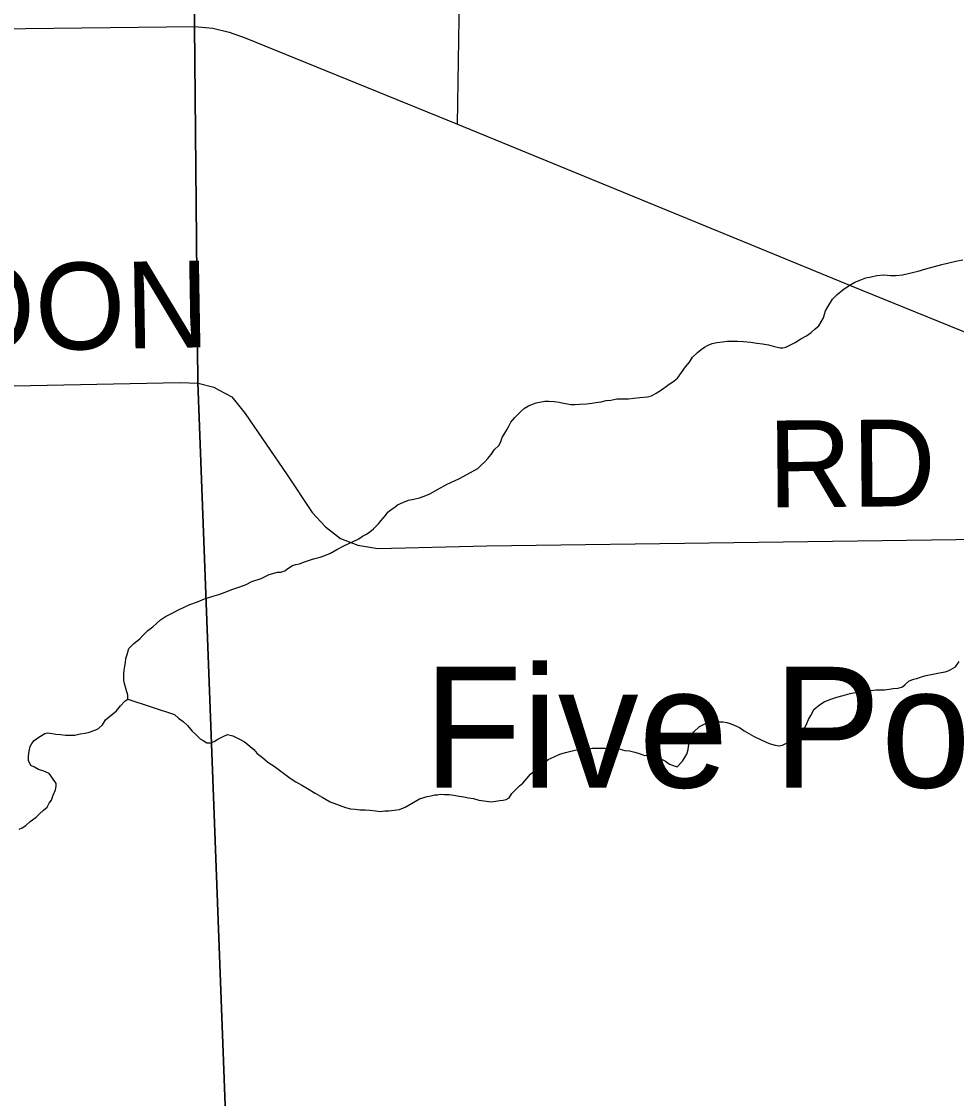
# Model space of a CAD drawing. Extents: x -59 to 82, y -3 to 49.
# Drawn here: x -50.668 to -50.056, y 43.234 to 43.939 of the extents above; entities that cross this region are included whole.
import ezdxf

# ---------------------------------------------------------------- set-up
doc = ezdxf.new("R2010")
doc.units = 0
for name, color, linetype in [('GM_X_Corporation', 7, 'Continuous'), ('GM_X_County_Road', 7, 'Continuous'), ('GM_X_County_Road_Text', 7, 'Continuous'), ('GM_X_Minor_River', 7, 'Continuous'), ('GM_X_State_Route', 7, 'Continuous'), ('GM_X_Township_Road', 7, 'Continuous'), ('GM_X_Unincorporated_Text', 7, 'Continuous')]:
    doc.layers.add(name, color=color, linetype=linetype)

msp = doc.modelspace()

# ---------------------------------------------------------------- linework, layer by layer
at = {"layer": 'GM_X_Corporation'}
for p, q in [((-50.55461, 43.9364), (-50.55326, 44.22179)), ((-50.55326, 44.22179), (-50.55461, 43.9364)), ((-50.55225, 43.7029), (-50.55461, 43.9364)), ((-50.55461, 43.9364), (-50.55225, 43.7029)), ((-50.52912, 43.09163), (-50.55225, 43.7029)), ((-50.55225, 43.7029), (-50.52912, 43.09163))]:
    msp.add_line(p, q, dxfattribs=at)
at = {"layer": 'GM_X_County_Road'}
for p, q in [((-50.75944, 43.69919), (-50.56412, 43.70278)), ((-50.56412, 43.70278), (-50.55205, 43.70234)), ((-50.55205, 43.70234), (-50.54176, 43.69974)), ((-50.54176, 43.69974), (-50.53843, 43.69794)), ((-50.53843, 43.69794), (-50.53011, 43.69342)), ((-50.53011, 43.69342), (-50.52143, 43.68269)), ((-50.52143, 43.68269), (-50.49381, 43.6425)), ((-50.49381, 43.6425), (-50.4776, 43.61784)), ((-50.4776, 43.61784), (-50.46893, 43.60848)), ((-50.46893, 43.60848), (-50.45912, 43.60071)), ((-50.45912, 43.60071), (-50.4477, 43.59637)), ((-50.36324, 43.59592), (-50.00652, 43.60075)), ((-50.4477, 43.59637), (-50.43469, 43.59432)), ((-50.43469, 43.59432), (-50.36324, 43.59592))]:
    msp.add_line(p, q, dxfattribs=at)
at = {"layer": 'GM_X_Minor_River'}
for p, q in [((-50.07058, 43.77883), (-50.06565, 43.78001)), ((-50.06565, 43.78001), (-50.06111, 43.78118)), ((-50.06111, 43.78118), (-50.05656, 43.78235)), ((-50.05656, 43.78235), (-50.05201, 43.78314)), ((-50.11191, 43.77208), (-50.10812, 43.77287)), ((-50.10812, 43.77287), (-50.10357, 43.77328)), ((-50.10357, 43.77328), (-50.09939, 43.77293)), ((-50.09939, 43.77293), (-50.09559, 43.77295)), ((-50.09559, 43.77295), (-50.09142, 43.77336)), ((-50.09142, 43.77336), (-50.08118, 43.77572)), ((-50.08118, 43.77572), (-50.07626, 43.77727)), ((-50.07626, 43.77727), (-50.07058, 43.77883)), ((-50.13045, 43.76358), (-50.1263, 43.76627)), ((-50.1263, 43.76627), (-50.12252, 43.76858)), ((-50.12252, 43.76858), (-50.11873, 43.77013)), ((-50.11873, 43.77013), (-50.11532, 43.77129)), ((-50.11532, 43.77129), (-50.11191, 43.77208)), ((-50.13724, 43.75745), (-50.13422, 43.76051)), ((-50.13422, 43.76051), (-50.13045, 43.76358)), ((-50.14173, 43.74981), (-50.14023, 43.75249)), ((-50.14023, 43.75249), (-50.13724, 43.75745)), ((-50.14471, 43.74257), (-50.14321, 43.74524)), ((-50.14321, 43.74524), (-50.14247, 43.74753)), ((-50.14247, 43.74753), (-50.14173, 43.74981)), ((-50.15111, 43.73568), (-50.14847, 43.73798)), ((-50.14847, 43.73798), (-50.14621, 43.7399)), ((-50.14621, 43.7399), (-50.14471, 43.74257)), ((-50.16169, 43.72914), (-50.15791, 43.73145)), ((-50.15791, 43.73145), (-50.15413, 43.73338)), ((-50.15413, 43.73338), (-50.15111, 43.73568)), ((-50.22543, 43.72261), (-50.22317, 43.72453)), ((-50.22317, 43.72453), (-50.2209, 43.72606)), ((-50.2209, 43.72606), (-50.21863, 43.72722)), ((-50.21863, 43.72722), (-50.21598, 43.72838)), ((-50.21598, 43.72838), (-50.21295, 43.72916)), ((-50.21295, 43.72916), (-50.20916, 43.72957)), ((-50.20916, 43.72957), (-50.20613, 43.72997)), ((-50.20613, 43.72997), (-50.20271, 43.72999)), ((-50.20271, 43.72999), (-50.19929, 43.73002)), ((-50.19929, 43.73002), (-50.19549, 43.72967)), ((-50.19549, 43.72967), (-50.19055, 43.72932)), ((-50.19055, 43.72932), (-50.18675, 43.72859)), ((-50.18675, 43.72859), (-50.18295, 43.72823)), ((-50.18295, 43.72823), (-50.17915, 43.7275)), ((-50.17915, 43.7275), (-50.1761, 43.72676)), ((-50.1761, 43.72676), (-50.17344, 43.72602)), ((-50.17344, 43.72602), (-50.17154, 43.72565)), ((-50.17154, 43.72565), (-50.16964, 43.72566)), ((-50.16964, 43.72566), (-50.16774, 43.72606)), ((-50.16774, 43.72606), (-50.16509, 43.72722)), ((-50.16509, 43.72722), (-50.16169, 43.72914)), ((-50.23069, 43.71611), (-50.22883, 43.71955)), ((-50.22883, 43.71955), (-50.22543, 43.72261)), ((-50.23859, 43.70579), (-50.23333, 43.71305)), ((-50.23333, 43.71305), (-50.23069, 43.71611)), ((-50.24501, 43.70118), (-50.24085, 43.70387)), ((-50.24085, 43.70387), (-50.23859, 43.70579)), ((-50.25558, 43.69426), (-50.25255, 43.6958)), ((-50.25255, 43.6958), (-50.24916, 43.69811)), ((-50.24916, 43.69811), (-50.24501, 43.70118)), ((-50.33603, 43.68761), (-50.33338, 43.68877)), ((-50.33338, 43.68877), (-50.33111, 43.68955)), ((-50.33111, 43.68955), (-50.32883, 43.68995)), ((-50.32883, 43.68995), (-50.32542, 43.69073)), ((-50.32542, 43.69073), (-50.32276, 43.69075)), ((-50.32276, 43.69075), (-50.31934, 43.69039)), ((-50.31934, 43.69039), (-50.31592, 43.69004)), ((-50.31592, 43.69004), (-50.31326, 43.68929)), ((-50.31326, 43.68929), (-50.3106, 43.68893)), ((-50.3106, 43.68893), (-50.30832, 43.68857)), ((-50.30832, 43.68857), (-50.30566, 43.68859)), ((-50.30566, 43.68859), (-50.30262, 43.68861)), ((-50.30262, 43.68861), (-50.29807, 43.68902)), ((-50.29807, 43.68902), (-50.29465, 43.68942)), ((-50.29465, 43.68942), (-50.292, 43.68982)), ((-50.292, 43.68982), (-50.28858, 43.69023)), ((-50.28858, 43.69023), (-50.28517, 43.69101)), ((-50.28517, 43.69101), (-50.28214, 43.69141)), ((-50.28214, 43.69141), (-50.27835, 43.6922)), ((-50.27835, 43.6922), (-50.27455, 43.69223)), ((-50.27455, 43.69223), (-50.27075, 43.69225)), ((-50.27075, 43.69225), (-50.26734, 43.69266)), ((-50.26734, 43.69266), (-50.26317, 43.69307)), ((-50.26317, 43.69307), (-50.25823, 43.69348)), ((-50.25823, 43.69348), (-50.25558, 43.69426)), ((-50.34508, 43.67995), (-50.34282, 43.68224)), ((-50.34282, 43.68224), (-50.34094, 43.68416)), ((-50.34094, 43.68416), (-50.33867, 43.68607)), ((-50.33867, 43.68607), (-50.33603, 43.68761)), ((-50.34921, 43.67383), (-50.34771, 43.67688)), ((-50.34771, 43.67688), (-50.34508, 43.67995)), ((-50.35333, 43.66696), (-50.35145, 43.66963)), ((-50.35145, 43.66963), (-50.35033, 43.67192)), ((-50.35033, 43.67192), (-50.34921, 43.67383)), ((-50.3582, 43.65894), (-50.35556, 43.66162)), ((-50.35556, 43.66162), (-50.35444, 43.66353)), ((-50.35444, 43.66353), (-50.35333, 43.66696)), ((-50.36459, 43.65091), (-50.36271, 43.6532)), ((-50.36271, 43.6532), (-50.36046, 43.65588)), ((-50.36046, 43.65588), (-50.3582, 43.65894)), ((-50.38159, 43.63976), (-50.36911, 43.64669)), ((-50.36911, 43.64669), (-50.36723, 43.64861)), ((-50.36723, 43.64861), (-50.36459, 43.65091)), ((-50.38915, 43.63628), (-50.38159, 43.63976)), ((-50.4005, 43.63012), (-50.39558, 43.63282)), ((-50.39558, 43.63282), (-50.38915, 43.63628)), ((-50.4183, 43.62429), (-50.41451, 43.62584)), ((-50.41451, 43.62584), (-50.4111, 43.62663)), ((-50.4111, 43.62663), (-50.40731, 43.62741)), ((-50.40731, 43.62741), (-50.40428, 43.62857)), ((-50.40428, 43.62857), (-50.4005, 43.63012)), ((-50.42962, 43.61585), (-50.42812, 43.61814)), ((-50.42812, 43.61814), (-50.42586, 43.61968)), ((-50.42586, 43.61968), (-50.42359, 43.62121)), ((-50.42359, 43.62121), (-50.4217, 43.62275)), ((-50.4217, 43.62275), (-50.4183, 43.62429)), ((-50.43414, 43.61049), (-50.43263, 43.61241)), ((-50.43263, 43.61241), (-50.42962, 43.61585)), ((-50.44205, 43.60359), (-50.43979, 43.60513)), ((-50.43979, 43.60513), (-50.43752, 43.60705)), ((-50.43752, 43.60705), (-50.43414, 43.61049)), ((-50.45642, 43.59627), (-50.45113, 43.59859)), ((-50.45113, 43.59859), (-50.44696, 43.60052)), ((-50.44696, 43.60052), (-50.4447, 43.60243)), ((-50.4447, 43.60243), (-50.44205, 43.60359)), ((-50.47231, 43.58855), (-50.46928, 43.58971)), ((-50.46928, 43.58971), (-50.4655, 43.59126)), ((-50.4655, 43.59126), (-50.46134, 43.59357)), ((-50.46134, 43.59357), (-50.45642, 43.59627)), ((-50.49351, 43.58118), (-50.49049, 43.5831)), ((-50.49049, 43.5831), (-50.48822, 43.58388)), ((-50.48822, 43.58388), (-50.48594, 43.58427)), ((-50.48594, 43.58427), (-50.48329, 43.58543)), ((-50.48329, 43.58543), (-50.48064, 43.58621)), ((-50.48064, 43.58621), (-50.47799, 43.58699)), ((-50.47799, 43.58699), (-50.47572, 43.58777)), ((-50.47572, 43.58777), (-50.47231, 43.58855)), ((-50.51093, 43.57459), (-50.50563, 43.57729)), ((-50.50563, 43.57729), (-50.50033, 43.57885)), ((-50.50033, 43.57885), (-50.49805, 43.57886)), ((-50.49805, 43.57886), (-50.4954, 43.57964)), ((-50.4954, 43.57964), (-50.49351, 43.58118)), ((-50.52948, 43.56761), (-50.52493, 43.56917)), ((-50.52493, 43.56917), (-50.52077, 43.57072)), ((-50.52077, 43.57072), (-50.51699, 43.57264)), ((-50.51699, 43.57264), (-50.51093, 43.57459)), ((-50.55258, 43.55947), (-50.54804, 43.5614)), ((-50.54804, 43.5614), (-50.54311, 43.56295)), ((-50.54311, 43.56295), (-50.53856, 43.56413)), ((-50.53856, 43.56413), (-50.5344, 43.56568)), ((-50.5344, 43.56568), (-50.52948, 43.56761)), ((-50.56506, 43.55406), (-50.56128, 43.55598)), ((-50.56128, 43.55598), (-50.5575, 43.55753)), ((-50.5575, 43.55753), (-50.55258, 43.55947)), ((-50.57942, 43.54521), (-50.57678, 43.54751)), ((-50.57678, 43.54751), (-50.57338, 43.54981)), ((-50.57338, 43.54981), (-50.5696, 43.55174)), ((-50.5696, 43.55174), (-50.56506, 43.55406)), ((-50.58809, 43.53754), (-50.58508, 43.54061)), ((-50.58508, 43.54061), (-50.58168, 43.54291)), ((-50.58168, 43.54291), (-50.57942, 43.54521)), ((-50.59412, 43.53218), (-50.59224, 43.53371)), ((-50.59224, 43.53371), (-50.59035, 43.53524)), ((-50.59035, 43.53524), (-50.58809, 43.53754)), ((-50.59862, 43.52492), (-50.59751, 43.52873)), ((-50.59751, 43.52873), (-50.59412, 43.53218)), ((-50.60008, 43.5173), (-50.59972, 43.51959)), ((-50.59972, 43.51959), (-50.59936, 43.52225)), ((-50.59936, 43.52225), (-50.59862, 43.52492)), ((-50.0567, 43.51693), (-50.05445, 43.52037)), ((-50.6008, 43.51235), (-50.60044, 43.51464)), ((-50.60078, 43.50969), (-50.6008, 43.51235)), ((-50.60044, 43.51464), (-50.60008, 43.5173)), ((-50.07602, 43.51109), (-50.06616, 43.51306)), ((-50.06616, 43.51306), (-50.06351, 43.51346)), ((-50.06351, 43.51346), (-50.06161, 43.51423)), ((-50.06161, 43.51423), (-50.05972, 43.51501)), ((-50.05972, 43.51501), (-50.0567, 43.51693)), ((-50.60076, 43.50779), (-50.60078, 43.50969)), ((-50.60037, 43.50589), (-50.60076, 43.50779)), ((-50.5992, 43.5021), (-50.60037, 43.50589)), ((-50.09153, 43.50375), (-50.08964, 43.50529)), ((-50.08964, 43.50529), (-50.087, 43.50759)), ((-50.087, 43.50759), (-50.08397, 43.50875)), ((-50.08397, 43.50875), (-50.08208, 43.50914)), ((-50.08208, 43.50914), (-50.07905, 43.51031)), ((-50.07905, 43.51031), (-50.07602, 43.51109)), ((-50.59803, 43.4983), (-50.5992, 43.5021)), ((-50.59801, 43.49564), (-50.59803, 43.4983)), ((-50.13438, 43.49699), (-50.13021, 43.49816)), ((-50.13021, 43.49816), (-50.12567, 43.49933)), ((-50.12567, 43.49933), (-50.12339, 43.49973)), ((-50.12339, 43.49973), (-50.12112, 43.50013)), ((-50.12112, 43.50013), (-50.11884, 43.50052)), ((-50.11884, 43.50052), (-50.11657, 43.50092)), ((-50.11657, 43.50092), (-50.11429, 43.50131)), ((-50.11429, 43.50131), (-50.11201, 43.50133)), ((-50.11201, 43.50133), (-50.10898, 43.50173)), ((-50.10898, 43.50173), (-50.10594, 43.50175)), ((-50.10594, 43.50175), (-50.10328, 43.50177)), ((-50.10328, 43.50177), (-50.10025, 43.50217)), ((-50.10025, 43.50217), (-50.09759, 43.50257)), ((-50.09759, 43.50257), (-50.09418, 43.50298)), ((-50.09418, 43.50298), (-50.09153, 43.50375)), ((-50.60554, 43.48799), (-50.60291, 43.49142)), ((-50.60291, 43.49142), (-50.5999, 43.49449)), ((-50.5999, 43.49449), (-50.59801, 43.49564)), ((-50.59801, 43.49564), (-50.56755, 43.48559)), ((-50.14951, 43.4889), (-50.14573, 43.49197)), ((-50.14573, 43.49197), (-50.14271, 43.49389)), ((-50.14271, 43.49389), (-50.13893, 43.49544)), ((-50.13893, 43.49544), (-50.13438, 43.49699)), ((-50.61271, 43.48223), (-50.60554, 43.48799)), ((-50.56755, 43.48559), (-50.56487, 43.48333)), ((-50.15287, 43.48241), (-50.15137, 43.48508)), ((-50.15137, 43.48508), (-50.15025, 43.48699)), ((-50.15025, 43.48699), (-50.14951, 43.4889)), ((-50.61722, 43.47649), (-50.61458, 43.47879)), ((-50.61458, 43.47879), (-50.61271, 43.48223)), ((-50.56487, 43.48333), (-50.56182, 43.48107)), ((-50.56182, 43.48107), (-50.55914, 43.47842)), ((-50.55914, 43.47842), (-50.55607, 43.47464)), ((-50.22799, 43.47428), (-50.22422, 43.47773)), ((-50.22422, 43.47773), (-50.22082, 43.47965)), ((-50.22082, 43.47965), (-50.21703, 43.48082)), ((-50.21703, 43.48082), (-50.20868, 43.48088)), ((-50.20868, 43.48088), (-50.2064, 43.48052)), ((-50.2064, 43.48052), (-50.20411, 43.47977)), ((-50.20411, 43.47977), (-50.20144, 43.47865)), ((-50.20144, 43.47865), (-50.19801, 43.47715)), ((-50.19801, 43.47715), (-50.19496, 43.47489)), ((-50.15661, 43.47554), (-50.15511, 43.47745)), ((-50.15511, 43.47745), (-50.15399, 43.47974)), ((-50.15399, 43.47974), (-50.15287, 43.48241)), ((-50.6593, 43.46859), (-50.65628, 43.4709)), ((-50.65628, 43.4709), (-50.65251, 43.4732)), ((-50.65251, 43.4732), (-50.65061, 43.4736)), ((-50.65061, 43.4736), (-50.64757, 43.47324)), ((-50.64757, 43.47324), (-50.64529, 43.47288)), ((-50.64529, 43.47288), (-50.64225, 43.47252)), ((-50.64225, 43.47252), (-50.63883, 43.47216)), ((-50.63883, 43.47216), (-50.63617, 43.47218)), ((-50.63617, 43.47218), (-50.63275, 43.4722)), ((-50.63275, 43.4722), (-50.62934, 43.47299)), ((-50.62934, 43.47299), (-50.62593, 43.47339)), ((-50.62593, 43.47339), (-50.62328, 43.47417)), ((-50.62328, 43.47417), (-50.621, 43.47495)), ((-50.621, 43.47495), (-50.61911, 43.47572)), ((-50.61911, 43.47572), (-50.61722, 43.47649)), ((-50.55607, 43.47464), (-50.55378, 43.47276)), ((-50.55378, 43.47276), (-50.55071, 43.46974)), ((-50.53932, 43.46943), (-50.53629, 43.47098)), ((-50.53629, 43.47098), (-50.53289, 43.47252)), ((-50.53289, 43.47252), (-50.52947, 43.47179)), ((-50.52947, 43.47179), (-50.52718, 43.47066)), ((-50.52718, 43.47066), (-50.52413, 43.46916)), ((-50.23023, 43.46932), (-50.22949, 43.47161)), ((-50.22949, 43.47161), (-50.22799, 43.47428)), ((-50.19496, 43.47489), (-50.18886, 43.47151)), ((-50.18886, 43.47151), (-50.18352, 43.46889)), ((-50.16339, 43.46903), (-50.16113, 43.47095)), ((-50.16113, 43.47095), (-50.15887, 43.47324)), ((-50.15887, 43.47324), (-50.15661, 43.47554)), ((-50.66267, 43.46172), (-50.66193, 43.46477)), ((-50.66193, 43.46477), (-50.66081, 43.46668)), ((-50.66081, 43.46668), (-50.6593, 43.46859)), ((-50.55071, 43.46974), (-50.5488, 43.46861)), ((-50.5488, 43.46861), (-50.54652, 43.4671)), ((-50.54652, 43.4671), (-50.54386, 43.46712)), ((-50.54386, 43.46712), (-50.54159, 43.4679)), ((-50.54159, 43.4679), (-50.53932, 43.46943)), ((-50.52413, 43.46916), (-50.52184, 43.46766)), ((-50.52184, 43.46766), (-50.51993, 43.46615)), ((-50.51993, 43.46615), (-50.51802, 43.46464)), ((-50.51802, 43.46464), (-50.51572, 43.46276)), ((-50.51572, 43.46276), (-50.51342, 43.46011)), ((-50.3118, 43.46076), (-50.30194, 43.46311)), ((-50.30194, 43.46311), (-50.29929, 43.46313)), ((-50.29929, 43.46313), (-50.29663, 43.46315)), ((-50.29663, 43.46315), (-50.29435, 43.46355)), ((-50.29435, 43.46355), (-50.29208, 43.46356)), ((-50.29208, 43.46356), (-50.2898, 43.46358)), ((-50.2898, 43.46358), (-50.286, 43.46361)), ((-50.286, 43.46361), (-50.28258, 43.46325)), ((-50.28258, 43.46325), (-50.27916, 43.46327)), ((-50.27916, 43.46327), (-50.27612, 43.46292)), ((-50.27612, 43.46292), (-50.27308, 43.46217)), ((-50.23243, 43.4598), (-50.23169, 43.46285)), ((-50.23169, 43.46285), (-50.23133, 43.46475)), ((-50.23133, 43.46475), (-50.23097, 43.46703)), ((-50.23097, 43.46703), (-50.23023, 43.46932)), ((-50.18352, 43.46889), (-50.17857, 43.46664)), ((-50.17857, 43.46664), (-50.17476, 43.46552)), ((-50.17476, 43.46552), (-50.1721, 43.46516)), ((-50.1721, 43.46516), (-50.16982, 43.46556)), ((-50.16982, 43.46556), (-50.1668, 43.4671)), ((-50.1668, 43.4671), (-50.16339, 43.46903)), ((-50.66302, 43.45868), (-50.66267, 43.46172)), ((-50.663, 43.45564), (-50.66302, 43.45868)), ((-50.51342, 43.46011), (-50.50998, 43.45747)), ((-50.50998, 43.45747), (-50.50654, 43.45445)), ((-50.32655, 43.45343), (-50.32315, 43.45612)), ((-50.32315, 43.45612), (-50.31937, 43.45805)), ((-50.31937, 43.45805), (-50.31558, 43.4596)), ((-50.31558, 43.4596), (-50.3118, 43.46076)), ((-50.27308, 43.46217), (-50.27004, 43.46182)), ((-50.27004, 43.46182), (-50.26661, 43.46108)), ((-50.26661, 43.46108), (-50.26433, 43.46034)), ((-50.26433, 43.46034), (-50.26242, 43.45959)), ((-50.26242, 43.45959), (-50.26014, 43.45884)), ((-50.26014, 43.45884), (-50.25711, 43.45924)), ((-50.25711, 43.45924), (-50.25368, 43.45889)), ((-50.25368, 43.45889), (-50.25178, 43.45814)), ((-50.25178, 43.45814), (-50.24949, 43.45664)), ((-50.24949, 43.45664), (-50.24644, 43.45514)), ((-50.23543, 43.45521), (-50.23355, 43.45789)), ((-50.23355, 43.45789), (-50.23243, 43.4598)), ((-50.66145, 43.45223), (-50.663, 43.45564)), ((-50.65916, 43.4511), (-50.66145, 43.45223)), ((-50.65649, 43.4496), (-50.65916, 43.4511)), ((-50.65307, 43.44848), (-50.65649, 43.4496)), ((-50.50654, 43.45445), (-50.50234, 43.45182)), ((-50.50234, 43.45182), (-50.49891, 43.44918)), ((-50.49891, 43.44918), (-50.49547, 43.44655)), ((-50.33485, 43.44653), (-50.33221, 43.44883)), ((-50.33221, 43.44883), (-50.32956, 43.45075)), ((-50.32956, 43.45075), (-50.32655, 43.45343)), ((-50.24644, 43.45514), (-50.24377, 43.45325)), ((-50.24377, 43.45325), (-50.24072, 43.45214)), ((-50.24072, 43.45214), (-50.23882, 43.45139)), ((-50.23882, 43.45139), (-50.23543, 43.45521)), ((-50.64964, 43.44699), (-50.65307, 43.44848)), ((-50.64772, 43.44472), (-50.64964, 43.44699)), ((-50.64503, 43.44055), (-50.64772, 43.44472)), ((-50.49547, 43.44655), (-50.49203, 43.44391)), ((-50.49203, 43.44391), (-50.48821, 43.44165)), ((-50.48821, 43.44165), (-50.4844, 43.4394)), ((-50.33974, 43.44079), (-50.3371, 43.44385)), ((-50.3371, 43.44385), (-50.33485, 43.44653)), ((-50.64686, 43.43293), (-50.64537, 43.43637)), ((-50.64537, 43.43637), (-50.64501, 43.43865)), ((-50.64501, 43.43865), (-50.64503, 43.44055)), ((-50.4844, 43.4394), (-50.48058, 43.43714)), ((-50.48058, 43.43714), (-50.47562, 43.43414)), ((-50.3469, 43.4339), (-50.34426, 43.43658)), ((-50.34426, 43.43658), (-50.342, 43.43888)), ((-50.342, 43.43888), (-50.33974, 43.44079)), ((-50.65098, 43.42492), (-50.64948, 43.42759)), ((-50.64948, 43.42759), (-50.64797, 43.4295)), ((-50.64797, 43.4295), (-50.64686, 43.43293)), ((-50.47562, 43.43414), (-50.47104, 43.43151)), ((-50.47104, 43.43151), (-50.4657, 43.4285)), ((-50.4657, 43.4285), (-50.4558, 43.42477)), ((-50.41253, 43.42735), (-50.40724, 43.43043)), ((-50.40724, 43.43043), (-50.40232, 43.43199)), ((-50.40232, 43.43199), (-50.40004, 43.43238)), ((-50.40004, 43.43238), (-50.39739, 43.43317)), ((-50.39739, 43.43317), (-50.39549, 43.43318)), ((-50.39549, 43.43318), (-50.3936, 43.43357)), ((-50.3936, 43.43357), (-50.39094, 43.43321)), ((-50.39094, 43.43321), (-50.3879, 43.43323)), ((-50.3879, 43.43323), (-50.38486, 43.43287)), ((-50.38486, 43.43287), (-50.38143, 43.43214)), ((-50.38143, 43.43214), (-50.3784, 43.43177)), ((-50.3784, 43.43177), (-50.37535, 43.43104)), ((-50.37535, 43.43104), (-50.37193, 43.43068)), ((-50.37193, 43.43068), (-50.36851, 43.42956)), ((-50.36851, 43.42956), (-50.36356, 43.42884)), ((-50.36356, 43.42884), (-50.36052, 43.42848)), ((-50.36052, 43.42848), (-50.35749, 43.42888)), ((-50.35749, 43.42888), (-50.35483, 43.42928)), ((-50.35483, 43.42928), (-50.35256, 43.42968)), ((-50.35256, 43.42968), (-50.35066, 43.43007)), ((-50.35066, 43.43007), (-50.34877, 43.43122)), ((-50.34877, 43.43122), (-50.3469, 43.4339)), ((-50.65814, 43.4184), (-50.65588, 43.4207)), ((-50.65588, 43.4207), (-50.65324, 43.423)), ((-50.65324, 43.423), (-50.65098, 43.42492)), ((-50.4558, 43.42477), (-50.45238, 43.42403)), ((-50.45238, 43.42403), (-50.44934, 43.42367)), ((-50.44934, 43.42367), (-50.4463, 43.42331)), ((-50.4463, 43.42331), (-50.44288, 43.42334)), ((-50.44288, 43.42334), (-50.43984, 43.42298)), ((-50.43984, 43.42298), (-50.43604, 43.42263)), ((-50.43604, 43.42263), (-50.433, 43.42227)), ((-50.433, 43.42227), (-50.42996, 43.42267)), ((-50.42996, 43.42267), (-50.4273, 43.42269)), ((-50.4273, 43.42269), (-50.42389, 43.42309)), ((-50.42389, 43.42309), (-50.42048, 43.4235)), ((-50.42048, 43.4235), (-50.41669, 43.42504)), ((-50.41669, 43.42504), (-50.41253, 43.42735)), ((-50.66493, 43.41303), (-50.66192, 43.41571)), ((-50.66192, 43.41571), (-50.65814, 43.4184)), ((-50.66909, 43.41072), (-50.6672, 43.41149)), ((-50.6672, 43.41149), (-50.66493, 43.41303))]:
    msp.add_line(p, q, dxfattribs=at)
at = {"layer": 'GM_X_State_Route'}
for p, q in [((-50.8908, 43.93185), (-50.55441, 43.93584)), ((-50.55441, 43.93584), (-50.54257, 43.93471)), ((-50.54257, 43.93471), (-50.53187, 43.93216)), ((-50.53187, 43.93216), (-50.52133, 43.92849)), ((-50.52133, 43.92849), (-50.38246, 43.87185)), ((-50.38246, 43.87185), (-50.18758, 43.79187)), ((-50.18758, 43.79187), (-50.12494, 43.76622)), ((-50.12494, 43.76622), (-49.77489, 43.62288))]:
    msp.add_line(p, q, dxfattribs=at)
at = {"layer": 'GM_X_Township_Road'}
msp.add_line((-50.38246, 43.87185), (-50.38081, 43.98894), dxfattribs=at)

# ---------------------------------------------------------------- texts
at = {"layer": 'GM_X_County_Road_Text'}
for s, rotation, p in [('HUNTOON', 0.97329, (-50.92848, 43.71945)), ('RD', 0.49552, (-50.17921, 43.6211))]:
    msp.add_text(s, height=0.056818, rotation=rotation, dxfattribs=at).set_placement(p)
at = {"layer": 'GM_X_Unincorporated_Text'}
msp.add_text('Five Points', height=0.0789773, rotation=0.00001, dxfattribs=at).set_placement((-50.40484, 43.43787))

doc.saveas('drawing.dxf')
